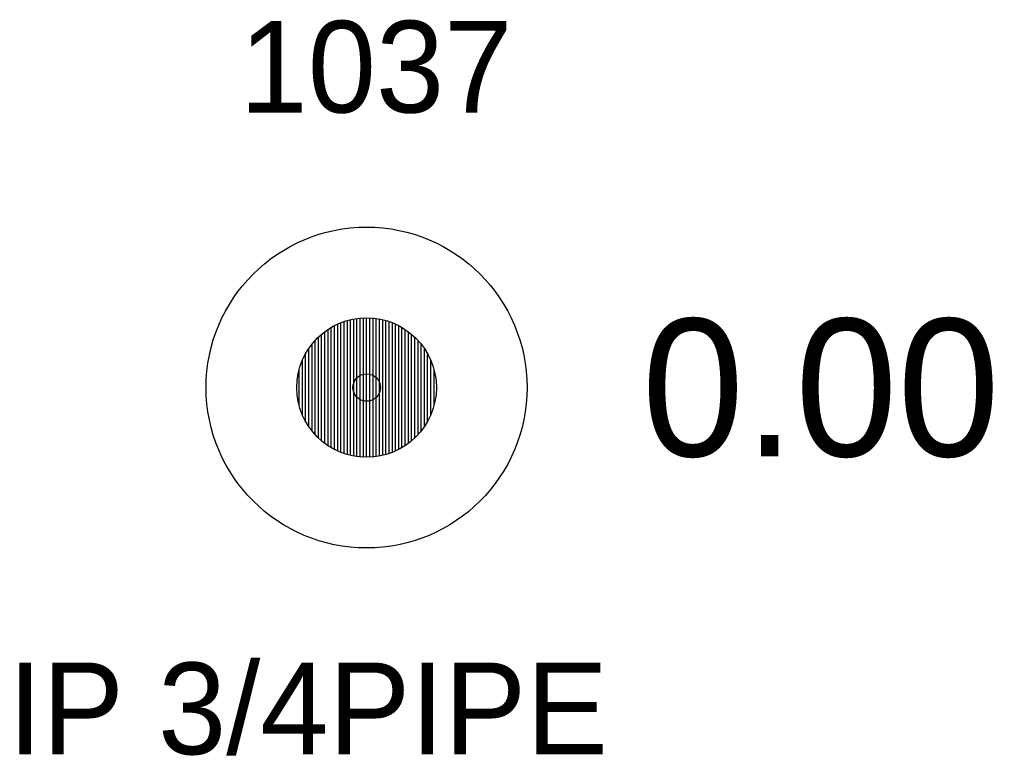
# Model space of a CAD drawing. Extents: x 2139392 to 2143384, y 505395 to 510520.
# Drawn here: x 2139728.06 to 2139738.67, y 505872.81 to 505880.84 of the extents above; entities that cross this region are included whole.
import ezdxf

# ---------------------------------------------------------------- set-up
doc = ezdxf.new("R2010")
doc.units = 0
for name, color, linetype in [('RD_EX_DV_Prop_txCode', 7, 'Continuous'), ('RD_EX_DV_PropPin', 7, 'Continuous'), ('RD_EX_TX_DV_Prop_ELEV', 7, 'Continuous'), ('RD_SMD_Locator', 7, 'Continuous')]:
    doc.layers.add(name, color=color, linetype=linetype)

msp = doc.modelspace()

# ---------------------------------------------------------------- linework, layer by layer
at = {"layer": 'RD_EX_DV_PropPin'}
for p, q in [((2139731.743, 505876.071), (2139731.743, 505877.579)), ((2139731.778, 505876.067), (2139731.778, 505877.583)), ((2139731.813, 505876.065), (2139731.813, 505877.585)), ((2139731.848, 505876.064), (2139731.848, 505877.586)), ((2139731.883, 505876.065), (2139731.883, 505877.585)), ((2139731.919, 505876.067), (2139731.919, 505877.583)), ((2139731.954, 505876.071), (2139731.954, 505877.579)), ((2139731.463, 505876.169), (2139731.463, 505877.482)), ((2139731.498, 505876.15), (2139731.498, 505877.501)), ((2139731.533, 505876.132), (2139731.533, 505877.518)), ((2139731.568, 505876.118), (2139731.568, 505877.533)), ((2139731.603, 505876.105), (2139731.603, 505877.546)), ((2139731.638, 505876.094), (2139731.638, 505877.557)), ((2139731.673, 505876.085), (2139731.673, 505877.566)), ((2139731.708, 505876.077), (2139731.708, 505877.573)), ((2139731.989, 505876.077), (2139731.989, 505877.573)), ((2139732.024, 505876.085), (2139732.024, 505877.566)), ((2139732.059, 505876.094), (2139732.059, 505877.557)), ((2139732.094, 505876.105), (2139732.094, 505877.546)), ((2139732.129, 505876.118), (2139732.129, 505877.533)), ((2139732.164, 505876.132), (2139732.164, 505877.518)), ((2139732.199, 505876.15), (2139732.199, 505877.501)), ((2139732.234, 505876.169), (2139732.234, 505877.482)), ((2139731.323, 505876.274), (2139731.323, 505877.376)), ((2139731.358, 505876.243), (2139731.358, 505877.407)), ((2139731.393, 505876.215), (2139731.393, 505877.435)), ((2139731.428, 505876.191), (2139731.428, 505877.46)), ((2139732.269, 505876.191), (2139732.269, 505877.46)), ((2139732.304, 505876.215), (2139732.304, 505877.435)), ((2139732.339, 505876.243), (2139732.339, 505877.407)), ((2139732.374, 505876.274), (2139732.374, 505877.376)), ((2139731.253, 505876.351), (2139731.253, 505877.299)), ((2139731.288, 505876.31), (2139731.288, 505877.34)), ((2139732.409, 505876.31), (2139732.409, 505877.34)), ((2139732.444, 505876.351), (2139732.444, 505877.299)), ((2139731.183, 505876.456), (2139731.183, 505877.195)), ((2139731.218, 505876.399), (2139731.218, 505877.252)), ((2139732.479, 505876.399), (2139732.479, 505877.252)), ((2139732.514, 505876.456), (2139732.514, 505877.195)), ((2139731.148, 505876.527), (2139731.148, 505877.123)), ((2139732.549, 505876.527), (2139732.549, 505877.123)), ((2139731.113, 505876.629), (2139731.113, 505877.021)), ((2139732.584, 505876.629), (2139732.584, 505877.021))]:
    msp.add_line(p, q, dxfattribs=at)
for radius in [1.75, 0.761]:
    msp.add_circle((2139731.848, 505876.825), radius, dxfattribs=at)
at = {"layer": 'RD_SMD_Locator'}
msp.add_circle((2139731.849, 505876.825), 0.15, dxfattribs=at)

# ---------------------------------------------------------------- texts
at = {"layer": 'RD_EX_DV_Prop_txCode'}
for s, p in [('1037', (2139730.463, 505879.825)), ('IP 3/4PIPE', (2139727.939, 505872.825))]:
    msp.add_text(s, height=1, dxfattribs=at).set_placement(p)
at = {"layer": 'RD_EX_TX_DV_Prop_ELEV'}
msp.add_text('0.00', height=1.5, dxfattribs=at).set_placement((2139734.849, 505876.075))

doc.saveas('drawing.dxf')
